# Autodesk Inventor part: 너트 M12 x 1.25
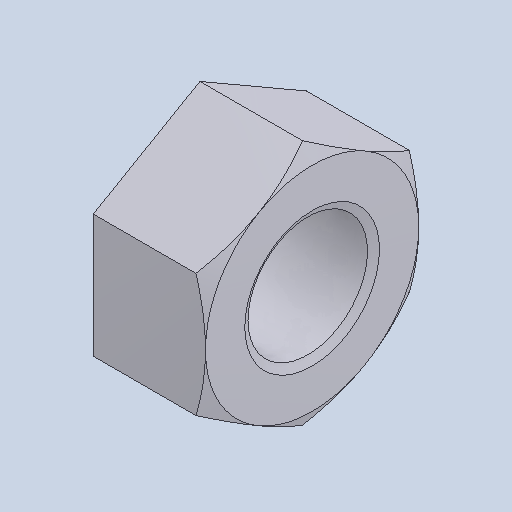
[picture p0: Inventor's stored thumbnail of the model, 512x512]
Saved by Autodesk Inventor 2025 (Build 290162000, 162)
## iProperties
Created: 2024-08
Part Number: 너트 M12 x 1.25
Material: 스테인리스강
Description: 6각 너트
Document SubType Name: Modeling
Designer: hsj03
Density: 8.08 g/cm^3
Appearance: 기본값
Author: jhkim
Sending System: Autodesk Inventor 2025
Preprocessor: ST-DEVELOPER v20
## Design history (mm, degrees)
feature "Solid1"
node "솔리드1"
